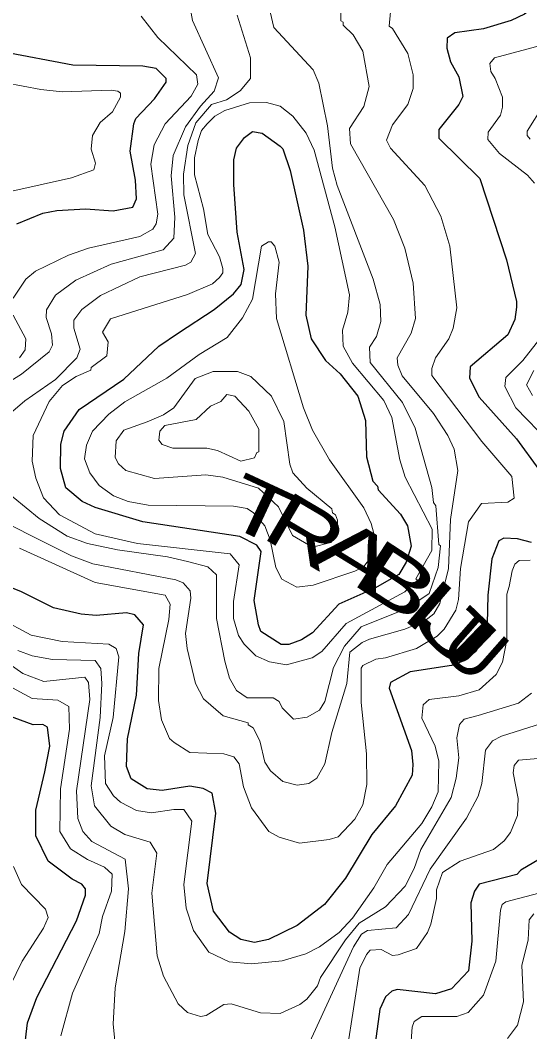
# Model space of a CAD drawing. Extents: x 423 to 448.8, y 7456.3 to 7484.
# Drawn here: x 424.349 to 425.089, y 7465.258 to 7466.728 of the extents above; entities that cross this region are included whole.
import ezdxf
from ezdxf.enums import TextEntityAlignment as Align

# ---------------------------------------------------------------- set-up
doc = ezdxf.new("R2010")
doc.units = 0
doc.header["$LTSCALE"] = 0.032
doc.layers.add('1', color=7, linetype='Continuous', lineweight=25)
doc.layers.add('2', color=7, linetype='Continuous', lineweight=13)
doc.layers.add('61', color=7, linetype='Continuous')

msp = doc.modelspace()

# ---------------------------------------------------------------- linework, layer by layer
at = {"layer": '1'}
for points in [[(425.1062, 7466.7555), (425.0814, 7466.7369), (425.0621, 7466.7277), (425.0219, 7466.7153), (424.9801, 7466.7098), (424.9692, 7466.7021), (424.9685, 7466.6875), (424.9739, 7466.6673), (424.9863, 7466.6457), (424.9917, 7466.617), (424.9863, 7466.6055), (424.9569, 7466.5691), (424.9569, 7466.5567), (425.0164, 7466.4979), (425.0551, 7466.3796), (425.0698, 7466.3193), (425.0698, 7466.3107), (425.0676, 7466.2931), (425.0574, 7466.2705), (425.0025, 7466.2241), (425.0018, 7466.2079), (425.0157, 7466.18), (425.0698, 7466.1197), (425.1023, 7466.0749)], [(424.3435, 7466.4322), (424.3815, 7466.4476), (424.4016, 7466.4515), (424.4433, 7466.4539), (424.4835, 7466.4508), (424.5121, 7466.4562), (424.5176, 7466.4685), (424.516, 7466.4956), (424.5083, 7466.5374), (424.5137, 7466.5776), (424.5168, 7466.5853), (424.5439, 7466.6139), (424.5609, 7466.638), (424.5609, 7466.6433), (424.5462, 7466.658), (424.5269, 7466.6611), (424.4248, 7466.6627), (424.3227, 7466.682)], [(425.0915, 7465.9689), (425.0714, 7465.9743), (425.0513, 7465.9751), (425.0443, 7465.9712), (425.0342, 7465.9449), (425.0281, 7465.8923), (425.0273, 7465.8506), (425.0219, 7465.8305), (425.011, 7465.8103), (424.9925, 7465.7964), (424.9755, 7465.7902), (424.9151, 7465.7809), (424.8865, 7465.7654), (424.885, 7465.7569), (424.9174, 7465.6665), (424.919, 7465.6464), (424.9182, 7465.6309), (424.8942, 7465.586), (424.8594, 7465.5442), (424.8215, 7465.4809), (424.7906, 7465.4429), (424.7512, 7465.412), (424.7094, 7465.3919), (424.6893, 7465.3873), (424.6692, 7465.3919), (424.6529, 7465.4027), (424.6297, 7465.4329), (424.6204, 7465.4731), (424.6328, 7465.5752), (424.6274, 7465.6046), (424.6143, 7465.6115), (424.5949, 7465.6146), (424.5547, 7465.6084), (424.533, 7465.6108), (424.5098, 7465.6255), (424.5029, 7465.6433), (424.5044, 7465.6835), (424.5176, 7465.7469), (424.5207, 7465.8073), (424.5276, 7465.849), (424.5152, 7465.8637), (424.5029, 7465.8668), (424.4588, 7465.8629), (424.4371, 7465.8645), (424.3969, 7465.8738)], [(424.3969, 7465.8738), (424.3505, 7465.897), (424.2654, 7465.9317)], [(424.3505, 7465.1962), (424.359, 7465.2705), (424.3729, 7465.3076), (424.4301, 7465.419), (424.4433, 7465.4561), (424.4433, 7465.4654), (424.4379, 7465.4723), (424.424, 7465.4793), (424.3892, 7465.5056), (424.3714, 7465.5427), (424.3714, 7465.5799), (424.3845, 7465.6355), (424.3915, 7465.6727), (424.3884, 7465.7005), (424.3814, 7465.7044), (424.3675, 7465.7036), (424.3211, 7465.7206)], [(425.25, 7465.6789), (425.2392, 7465.6417), (425.2268, 7465.6232), (425.2075, 7465.6116), (425.1518, 7465.6015), (425.1409, 7465.5906), (425.1271, 7465.5412), (425.117, 7465.5226), (425.1031, 7465.5087), (425.076, 7465.4924), (425.0706, 7465.4862), (425.0157, 7465.4723), (425.0087, 7465.4623), (425.0033, 7465.4453), (425.0048, 7465.3896), (425.0002, 7465.3462), (424.9754, 7465.3199), (424.9523, 7465.313), (424.8966, 7465.3192), (424.8888, 7465.3168), (424.8795, 7465.3084), (424.871, 7465.2906), (424.8587, 7465.1978)]]:
    msp.add_lwpolyline(points, dxfattribs=at)
msp.add_lwpolyline([(424.5786, 7466.2736), (424.6305, 7466.3077), (424.6583, 7466.3301), (424.6699, 7466.344), (424.6738, 7466.3657), (424.6637, 7466.4198), (424.6591, 7466.4894), (424.6591, 7466.525), (424.663, 7466.542), (424.6746, 7466.5575), (424.6861, 7466.566), (424.7001, 7466.5637), (424.7264, 7466.5451), (424.7302, 7466.5412), (424.7411, 7466.5096), (424.7604, 7466.4229), (424.7666, 7466.3703), (424.7635, 7466.2992), (424.7712, 7466.2651), (424.7921, 7466.2334), (424.8138, 7466.2141), (424.8393, 7466.1816), (424.8502, 7466.146), (424.8517, 7466.0934), (424.861, 7466.0579), (424.8679, 7466.0509), (424.8687, 7466.0455), (424.9012, 7466.0099), (424.9113, 7465.9929), (424.9167, 7465.9634), (424.9097, 7465.9403), (424.8989, 7465.9225), (424.8641, 7465.9024), (424.8115, 7465.8791), (424.7736, 7465.8374), (424.7574, 7465.8273), (424.7388, 7465.8204), (424.7279, 7465.8204), (424.6985, 7465.8397), (424.6947, 7465.849), (424.6885, 7465.8846), (424.6986, 7465.9558), (424.6923, 7465.965), (424.6676, 7465.9774), (424.5269, 7465.9991), (424.4573, 7466.0199), (424.4387, 7466.0285), (424.4147, 7466.0485), (424.407, 7466.0764), (424.4077, 7466.112), (424.4124, 7466.1306), (424.434, 7466.1623), (424.499, 7466.2063), (424.55, 7466.2543)], close=True, dxfattribs=at)
at = {"layer": '2'}
for points in [[(424.2592, 7466.1568), (424.3505, 7466.2133), (424.3907, 7466.2458), (424.3954, 7466.2559), (424.3938, 7466.2721), (424.3861, 7466.2961), (424.3868, 7466.3069), (424.4, 7466.3285), (424.4294, 7466.3502), (424.4805, 7466.3734), (424.5562, 7466.3943), (424.5717, 7466.4113), (424.5733, 7466.4415), (424.5678, 7466.5018), (424.5709, 7466.5312), (424.5887, 7466.573), (424.6104, 7466.6031), (424.6305, 7466.6248), (424.6367, 7466.6441), (424.5988, 7466.7277), (424.5934, 7466.7571)], [(424.8146, 7466.7454), (424.8146, 7466.7269), (424.8177, 7466.7253), (424.8177, 7466.7207), (424.8323, 7466.7068), (424.8463, 7466.6828), (424.8555, 7466.6318), (424.8478, 7466.6024), (424.827, 7466.5706), (424.8285, 7466.5482), (424.8911, 7466.4384), (424.9074, 7466.3966), (424.9198, 7466.3456), (424.9229, 7466.2945), (424.9166, 7466.2729), (424.8966, 7466.2373), (424.8973, 7466.2265), (424.9035, 7466.211), (424.9491, 7466.1561), (424.97, 7466.1244), (424.9793, 7466.1043), (424.9847, 7466.0733), (424.9739, 7466.0022), (424.9708, 7465.931), (424.9584, 7465.88), (424.9499, 7465.8652), (424.9368, 7465.8552), (424.9074, 7465.8428), (424.8564, 7465.8281), (424.8455, 7465.8235), (424.8275, 7465.8093), (424.8231, 7465.7639), (424.8014, 7465.6928), (424.7913, 7465.6471), (424.7798, 7465.6262), (424.7681, 7465.6185), (424.7512, 7465.6162), (424.7303, 7465.6216), (424.7124, 7465.6371), (424.704, 7465.6495), (424.697, 7465.6804), (424.687, 7465.6997), (424.68, 7465.7036), (424.68, 7465.7067), (424.6436, 7465.7167), (424.615, 7465.7415), (424.6034, 7465.7639), (424.591, 7465.815), (424.5887, 7465.8366), (424.5964, 7465.8877), (424.5957, 7465.8985), (424.5856, 7465.9101), (424.5748, 7465.9147), (424.4542, 7465.9379), (424.4232, 7465.9495), (424.2824, 7466.0199)], [(424.3188, 7466.0501), (424.376, 7466.0037), (424.417, 7465.9782), (424.4464, 7465.9673), (424.4897, 7465.958), (424.5624, 7465.948), (424.5918, 7465.941), (424.6212, 7465.9333), (424.6336, 7465.9217), (424.6336, 7465.8583), (424.6459, 7465.7964), (424.6529, 7465.7717), (424.663, 7465.7539), (424.6784, 7465.743), (424.7163, 7465.743), (424.7249, 7465.7376), (424.7295, 7465.7283), (424.7457, 7465.7121), (424.7658, 7465.7152), (424.7836, 7465.7252), (424.7913, 7465.7376), (424.8037, 7465.7871), (424.82, 7465.8184), (424.844, 7465.8463), (424.9105, 7465.873), (424.943, 7465.8946), (424.9561, 7465.9326), (424.9592, 7465.9642), (424.9569, 7465.9658), (424.9524, 7466.0222), (424.9492, 7466.0269), (424.9468, 7466.0486), (424.9228, 7466.1352), (424.9043, 7466.1723), (424.8571, 7466.2303), (424.8563, 7466.2528), (424.8664, 7466.2682), (424.8726, 7466.2899), (424.8718, 7466.3146), (424.8617, 7466.3518), (424.8091, 7466.4879), (424.8022, 7466.5127), (424.7952, 7466.5745), (424.7828, 7466.6364), (424.7744, 7466.6557), (424.7171, 7466.7176), (424.7117, 7466.74)], [(424.8865, 7466.74), (424.8849, 7466.7191), (424.8896, 7466.716), (424.912, 7466.6797), (424.9198, 7466.6488), (424.9198, 7466.6286), (424.912, 7466.6055), (424.8896, 7466.5761), (424.8811, 7466.5536), (424.8865, 7466.542), (424.9368, 7466.4879), (424.96, 7466.443), (424.9731, 7466.3997), (424.9832, 7466.31), (424.9778, 7466.2806), (424.9716, 7466.2651), (424.9522, 7466.2373), (424.9468, 7466.2218), (424.9468, 7466.2117), (425.0195, 7466.1158), (425.0629, 7466.0648), (425.0667, 7466.0331), (425.0575, 7466.0277), (425.0188, 7466.0253), (425.0002, 7465.999), (424.9886, 7465.931), (424.9855, 7465.8861), (424.9816, 7465.8707), (424.9646, 7465.8428), (424.9546, 7465.8327), (424.9244, 7465.8149), (424.8796, 7465.801), (424.8656, 7465.7995), (424.8463, 7465.7902), (424.844, 7465.7864), (424.844, 7465.7361), (424.8517, 7465.6618), (424.8525, 7465.617), (424.8463, 7465.5876), (424.8347, 7465.5667), (424.8107, 7465.5411), (424.7976, 7465.5373)], [(424.6637, 7466.7354), (424.6831, 7466.6735), (424.6831, 7466.6433), (424.6684, 7466.6255), (424.6483, 7466.6124), (424.6265, 7466.6057), (424.604, 7466.5787), (424.592, 7466.5457), (424.586, 7466.5044), (424.5864, 7466.474), (424.6034, 7466.3889), (424.5964, 7466.3765), (424.5887, 7466.3719), (424.5222, 7466.3548), (424.465, 7466.3278), (424.4379, 7466.3077), (424.4263, 7466.2922), (424.4263, 7466.2806), (424.4356, 7466.2497), (424.4309, 7466.2373), (424.4, 7466.2056), (424.3552, 7466.1746), (424.3311, 7466.1537)], [(424.3381, 7466.3239), (424.3567, 7466.3518), (424.3706, 7466.3633), (424.4186, 7466.3865), (424.448, 7466.3966), (424.5222, 7466.4136), (424.5415, 7466.4244), (424.5462, 7466.4322), (424.5485, 7466.4461), (424.5384, 7466.5188), (424.5431, 7466.5467), (424.5593, 7466.5776), (424.5972, 7466.6178), (424.6065, 7466.6349), (424.6049, 7466.6488), (424.5485, 7466.7029), (424.5245, 7466.7339)], [(425.0961, 7466.4909), (425.0861, 7466.5026), (425.0451, 7466.5343), (425.0281, 7466.5544), (425.0288, 7466.5652), (425.0466, 7466.59), (425.0497, 7466.6016), (425.0497, 7466.6163), (425.0389, 7466.6433), (425.0327, 7466.6534), (425.0312, 7466.665), (425.0381, 7466.6735), (425.1193, 7466.6951)], [(424.3273, 7466.6371), (424.3784, 7466.6271), (424.4093, 7466.624), (424.4805, 7466.6263), (424.4905, 7466.6248), (424.4944, 7466.6217), (424.4944, 7466.6163), (424.4828, 7466.5946), (424.4649, 7466.5792), (424.4534, 7466.5606), (424.4518, 7466.5405), (424.458, 7466.5204), (424.4557, 7466.5103), (424.4232, 7466.4987), (424.3319, 7466.4786)], [(425.0899, 7466.5552), (425.0853, 7466.5606), (425.0853, 7466.5668), (425.1092, 7466.6047)], [(424.3474, 7466.2373), (424.3559, 7466.2489), (424.3567, 7466.2651), (424.3381, 7466.2991)], [(425.1178, 7466.1143), (425.069, 7466.1646), (425.0528, 7466.1955), (425.0544, 7466.2087), (425.0791, 7466.2334), (425.1039, 7466.2651)], [(425.093, 7466.1824), (425.0845, 7466.1978), (425.0953, 7466.2187)], [(424.7976, 7465.5373), (424.7543, 7465.5319), (424.7249, 7465.5404), (424.7101, 7465.5489), (424.6846, 7465.583), (424.673, 7465.6139), (424.6668, 7465.6471), (424.6591, 7465.6572), (424.6444, 7465.6618), (424.5949, 7465.6634), (424.5725, 7465.6781), (424.5655, 7465.6842), (424.5539, 7465.7113), (424.5493, 7465.7392), (424.5501, 7465.7856), (424.5647, 7465.8568), (424.5663, 7465.8792), (424.5593, 7465.8923), (424.4573, 7465.9109), (424.3474, 7465.9604)], [(424.3195, 7465.8583), (424.3644, 7465.8343), (424.4093, 7465.825), (424.4774, 7465.8212), (424.4881, 7465.815), (424.492, 7465.8026), (424.4835, 7465.7144), (424.4711, 7465.6588), (424.4727, 7465.6185), (424.4843, 7465.6007), (424.4943, 7465.5914), (424.5176, 7465.5791), (424.5392, 7465.576), (424.5717, 7465.5806), (424.5864, 7465.5806), (424.598, 7465.5636), (424.5864, 7465.4716), (424.5895, 7465.4375), (424.6003, 7465.4051), (424.6228, 7465.3733), (424.6522, 7465.3594), (424.6846, 7465.3563), (424.7295, 7465.3609), (424.7635, 7465.371), (424.7836, 7465.381), (424.8122, 7465.402), (424.8316, 7465.4228), (424.8625, 7465.4669), (424.8819, 7465.501), (424.9321, 7465.5605), (424.9468, 7465.5845), (424.9561, 7465.6062), (424.9569, 7465.651), (424.9515, 7465.6727), (424.9321, 7465.7136), (424.9344, 7465.733), (424.943, 7465.7407), (424.9863, 7465.7461), (425.0157, 7465.7546), (425.0404, 7465.7771), (425.0497, 7465.7949), (425.0559, 7465.8274), (425.0559, 7465.8939), (425.059, 7465.9047), (425.0636, 7465.9279), (425.0675, 7465.9372), (425.0737, 7465.9426), (425.0899, 7465.9433)], [(424.3451, 7465.8119), (424.366, 7465.8041), (424.3954, 7465.7987), (424.4573, 7465.7972), (424.4657, 7465.7856), (424.4673, 7465.7639), (424.4649, 7465.7144), (424.4518, 7465.6154), (424.4564, 7465.586), (424.4804, 7465.5566), (424.5006, 7465.5442), (424.5376, 7465.5334), (424.5469, 7465.5172), (424.54, 7465.4592), (424.5477, 7465.3679), (424.557, 7465.3385), (424.5779, 7465.2983), (424.5918, 7465.2859), (424.6104, 7465.2797), (424.6189, 7465.2813), (424.6444, 7465.2975), (424.6553, 7465.2983), (424.6978, 7465.2851), (424.7264, 7465.2844), (424.755, 7465.2975), (424.7651, 7465.3053), (424.7805, 7465.3246), (424.785, 7465.3365), (424.8211, 7465.3915), (424.8413, 7465.4156), (424.8796, 7465.4391), (424.9082, 7465.4692), (424.9213, 7465.4948), (424.9306, 7465.5226), (424.9747, 7465.5984), (424.9824, 7465.6263), (424.9863, 7465.6557), (424.9832, 7465.685), (424.9871, 7465.7044), (424.994, 7465.7121), (425.0141, 7465.7175), (425.0729, 7465.7353), (425.0915, 7465.75)], [(424.3103, 7465.808), (424.3521, 7465.7786), (424.383, 7465.767), (424.4425, 7465.7732), (424.448, 7465.7654), (424.4495, 7465.7407), (424.4302, 7465.6077), (424.4325, 7465.5675), (424.4394, 7465.5489), (424.4526, 7465.5342), (424.5013, 7465.5087), (424.5059, 7465.4654), (424.5005, 7465.4035), (424.4866, 7465.3215), (424.4835, 7465.2689), (424.4866, 7465.2403)], [(424.3257, 7465.7639), (424.366, 7465.7422), (424.4031, 7465.7399), (424.4193, 7465.7307), (424.4201, 7465.6974), (424.4069, 7465.6108), (424.4062, 7465.5489), (424.4216, 7465.5234), (424.4464, 7465.5079), (424.4711, 7465.4971), (424.482, 7465.487), (424.4812, 7465.4623), (424.4681, 7465.4252), (424.4634, 7465.4004), (424.4247, 7465.3138), (424.4077, 7465.2519)], [(424.7635, 7465.2303), (424.8331, 7465.3811), (424.8447, 7465.3996), (424.8533, 7465.4051), (424.895, 7465.4089), (424.9128, 7465.4283), (424.9445, 7465.494), (424.9971, 7465.5682), (425.0141, 7465.6), (425.0195, 7465.6185), (425.025, 7465.6672), (425.035, 7465.6804), (425.0482, 7465.6873), (425.1062, 7465.7059)], [(424.8239, 7465.2318), (424.8424, 7465.3501), (424.8517, 7465.3702), (424.8571, 7465.3764), (424.8734, 7465.3772), (424.8896, 7465.3687), (424.8981, 7465.3694), (424.9244, 7465.3787), (424.9406, 7465.402), (424.9453, 7465.4143), (424.9538, 7465.4515), (424.9538, 7465.4638), (424.9623, 7465.4893), (424.9878, 7465.5056), (425.0365, 7465.5226), (425.052, 7465.535), (425.0613, 7465.5474), (425.0714, 7465.5721), (425.0721, 7465.5969), (425.0652, 7465.634), (425.0667, 7465.6448), (425.0729, 7465.6526), (425.1642, 7465.6603), (425.2021, 7465.6734)], [(424.3258, 7465.3076), (424.3513, 7465.3602), (424.3822, 7465.4081), (424.3891, 7465.4236), (424.3853, 7465.436), (424.3505, 7465.4716), (424.3389, 7465.4979)], [(425.1116, 7465.4615), (425.0544, 7465.4468), (425.0489, 7465.4429), (425.0466, 7465.4344), (425.0396, 7465.3602), (425.0218, 7465.3107), (424.9994, 7465.2859), (424.9832, 7465.2797), (424.9321, 7465.2797), (424.9213, 7465.2728), (424.9182, 7465.2643), (424.912, 7465.1777)], [(425.0953, 7465.429), (425.0884, 7465.4205), (425.0868, 7465.3911), (425.0776, 7465.354), (425.0799, 7465.3014), (425.0714, 7465.2673), (425.0567, 7465.248)]]:
    msp.add_lwpolyline(points, dxfattribs=at)
for points in [[(424.4297, 7466.2103), (424.4514, 7466.2195), (424.4518, 7466.2234), (424.4743, 7466.2403), (424.4766, 7466.2605), (424.4681, 7466.2744), (424.4797, 7466.2937), (424.5918, 7466.3293), (424.6282, 7466.3448), (424.6382, 7466.3541), (424.6429, 7466.361), (424.6429, 7466.3672), (424.6382, 7466.3842), (424.6212, 7466.4167), (424.615, 7466.4539), (424.6019, 7466.5034), (424.6019, 7466.5281), (424.6073, 7466.5529), (424.6119, 7466.5675), (424.6204, 7466.5776), (424.6312, 7466.5884), (424.646, 7466.5969), (424.6816, 7466.6078), (424.7063, 7466.6085), (424.7264, 7466.6031), (424.745, 7466.5884), (424.7643, 7466.5637), (424.7759, 7466.5389), (424.806, 7466.4276), (424.827, 7466.3286), (424.8246, 7466.3038), (424.8169, 7466.2775), (424.8177, 7466.2543), (424.8316, 7466.2296), (424.8772, 7466.1754), (424.8888, 7466.1507), (424.9004, 7466.0888), (424.9081, 7466.064), (424.9475, 7465.9883), (424.9468, 7465.9572), (424.9234, 7465.916), (424.9259, 7465.914), (424.9074, 7465.8969), (424.8223, 7465.8513), (424.7867, 7465.8103), (424.7728, 7465.801), (424.7357, 7465.791), (424.7109, 7465.7956), (424.6908, 7465.8042), (424.6738, 7465.8212), (424.666, 7465.8336), (424.6583, 7465.8583), (424.6583, 7465.8831), (424.6668, 7465.9364), (424.6537, 7465.9526), (424.5191, 7465.9673), (424.4573, 7465.9813), (424.4054, 7466.0091), (424.3822, 7466.0339), (424.3714, 7466.0625), (424.366, 7466.0872), (424.3675, 7466.1244), (424.3907, 7466.1739), (424.41, 7466.1971)], [(424.6494, 7466.2666), (424.6715, 7466.2953), (424.6862, 7466.3224), (424.6993, 7466.3997), (424.7094, 7466.4059), (424.7132, 7466.4059), (424.7186, 7466.3997), (424.7249, 7466.3765), (424.7194, 7466.3301), (424.721, 7466.2945), (424.7604, 7466.1646), (424.7736, 7466.1321), (424.7983, 7466.0888), (424.8478, 7466.0191), (424.8586, 7465.9967), (424.8648, 7465.9728), (424.8641, 7465.955), (424.8478, 7465.9341), (424.8347, 7465.9271), (424.7744, 7465.907), (424.7504, 7465.9039), (424.7287, 7465.9155), (424.7202, 7465.9326), (424.7117, 7465.9728), (424.704, 7465.9929), (424.6877, 7466.0122), (424.6785, 7466.0184), (424.6583, 7466.0215), (424.5346, 7466.023), (424.5052, 7466.0285), (424.4843, 7466.0369), (424.4634, 7466.0517), (424.4495, 7466.0702), (424.4418, 7466.0903), (424.4449, 7466.1105), (424.4534, 7466.1306), (424.4773, 7466.1553), (424.5006, 7466.1731), (424.5616, 7466.2079), (424.6088, 7466.2419)], [(424.6029, 7466.207), (424.629, 7466.2172), (424.6645, 7466.2172), (424.6838, 7466.2102), (424.714, 7466.1816), (424.7318, 7466.1445), (424.7403, 7466.0826), (424.7449, 7466.0702), (424.765, 7466.0478), (424.8014, 7466.0176), (424.8022, 7466.0122), (424.8068, 7466.0091), (424.8099, 7466.0014), (424.8091, 7465.9805), (424.7999, 7465.9689), (424.7736, 7465.9619), (424.7442, 7465.979), (424.7241, 7466.0207), (424.6947, 7466.0478), (424.6429, 7466.064), (424.6181, 7466.0671), (424.5439, 7466.0617), (424.5021, 7466.0733), (424.4912, 7466.0833), (424.4866, 7466.0926), (424.4881, 7466.1166), (424.499, 7466.1321), (424.533, 7466.1444), (424.557, 7466.1545), (424.5717, 7466.1646)], [(424.6403, 7466.1736), (424.6489, 7466.184), (424.6606, 7466.1816), (424.6808, 7466.1599), (424.6954, 7466.1336), (424.6954, 7466.1004), (424.6923, 7466.0996), (424.6892, 7466.0918), (424.6692, 7466.0872), (424.6351, 7466.1027), (424.6197, 7466.1058), (424.5702, 7466.1058), (424.5547, 7466.1112), (424.5501, 7466.1174), (424.5516, 7466.1306), (424.5585, 7466.139), (424.6042, 7466.1475), (424.6251, 7466.1669)]]:
    msp.add_lwpolyline(points, close=True, dxfattribs=at)

# ---------------------------------------------------------------- texts
at = {"layer": '61'}
for s, rotation, width, p in [('T', 335.026, 1.45, (424.6824, 7465.9795)), ('R', 329.478, 1.4, (424.7434, 7465.95)), ('A', 328.451, 1.6, (424.8171, 7465.9165)), ('B', 326.894, 1.6, (424.8744, 7465.8802)), ('I', 319.118, 1.55, (424.9168, 7465.8471)), ('J', 316.126, 2.2, (424.9553, 7465.8125))]:
    msp.add_text(s, height=0.08, rotation=rotation, dxfattribs=dict(at, width=width)).set_placement(p, align=Align.CENTER)
msp.add_text('U', height=0.08, rotation=318.659, dxfattribs=at).set_placement((424.9834, 7465.786), align=Align.CENTER)

doc.saveas('drawing.dxf')
